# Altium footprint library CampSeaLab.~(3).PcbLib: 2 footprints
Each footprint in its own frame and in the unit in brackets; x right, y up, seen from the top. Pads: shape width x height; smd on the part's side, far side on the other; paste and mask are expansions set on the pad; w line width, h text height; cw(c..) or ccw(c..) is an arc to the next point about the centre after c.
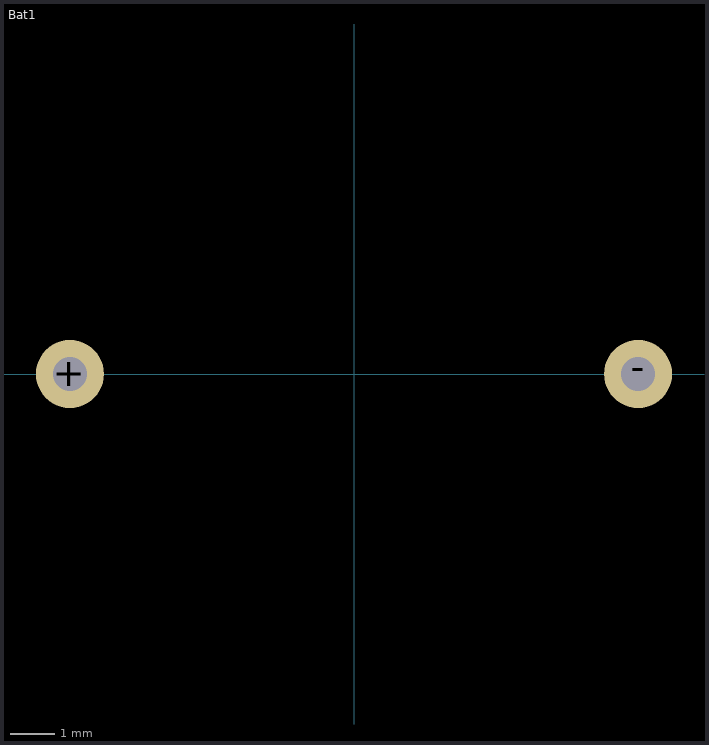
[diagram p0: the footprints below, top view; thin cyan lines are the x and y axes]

## Bat1 [mil] "Battery Holder 2xAA"
pads (2):
  round 60 hole 30: +(-250,0) -(250,0)

## PCBComponent_1 [mil]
